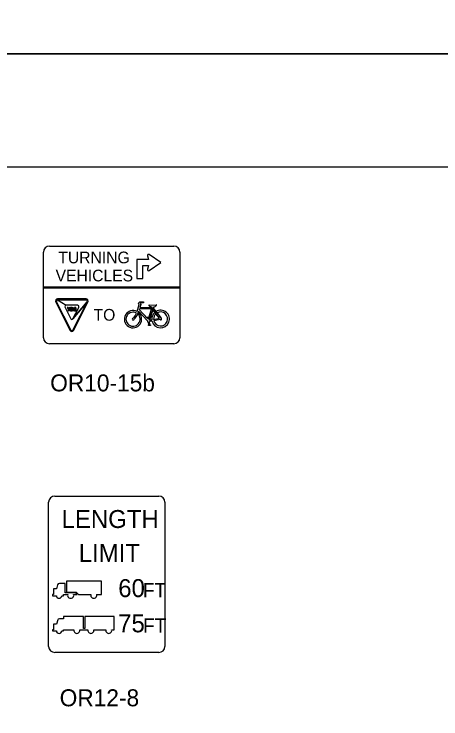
# Model space of a CAD drawing. Extents: x 42133 to 45533, y 41351 to 47951.
# Drawn here: x 42504.5 to 42693.1, y 44357.7 to 44668.9 of the extents above; entities that cross this region are included whole.
import ezdxf

# ---------------------------------------------------------------- set-up
doc = ezdxf.new("R2010")
doc.units = 0
for name, color, linetype in [('#plot_shape', 7, 'Continuous'), ('P_ODOT_PLAN_Border', 7, 'Continuous'), ('P_TRAF_SIGN_SignDetails', 7, 'Continuous')]:
    doc.layers.add(name, color=color, linetype=linetype)

msp = doc.modelspace()

# ---------------------------------------------------------------- linework, layer by layer
at = {"layer": '#plot_shape'}
for points in [[(42133.34, 44651.35), (43833.34, 44651.35), (43833.34, 45751.35), (42133.34, 45751.35)], [(42133.34, 43551.35), (43833.34, 43551.35), (43833.34, 44651.35), (42133.34, 44651.35)]]:
    msp.add_lwpolyline(points, close=True, dxfattribs=at)
at = {"layer": 'P_ODOT_PLAN_Border'}
msp.add_lwpolyline([(42208.34, 43601.35), (43808.34, 43601.35), (43808.34, 44601.35), (42208.34, 44601.35)], close=True, dxfattribs=at)
at = {"layer": 'P_TRAF_SIGN_SignDetails'}
for p, q in [((42517.51, 44526.03), (42517.51, 44563.81)), ((42520.2, 44566.5), (42575.09, 44566.5)), ((42577.79, 44563.81), (42577.79, 44526.03)), ((42517.53, 44547.84), (42517.53, 44548.41)), ((42517.53, 44548.41), (42577.73, 44548.41)), ((42577.73, 44548.41), (42577.73, 44547.84)), ((42577.73, 44547.84), (42517.53, 44547.84)), ((42529.59, 44529.46), (42523.27, 44541.88)), ((42536.39, 44543.18), (42523.74, 44543.18)), ((42536.39, 44543.18), (42523.74, 44543.18)), ((42536.39, 44543.18), (42523.74, 44543.18)), ((42523.74, 44542.81), (42527.51, 44540.34)), ((42523.74, 44542.81), (42536.39, 44542.81)), ((42530.54, 44534.4), (42536.86, 44541.88)), ((42536.86, 44541.88), (42530.54, 44529.46)), ((42536.86, 44541.88), (42530.54, 44534.4)), ((42536.39, 44543.18), (42536.39, 44543.18)), ((42536.39, 44543.18), (42536.39, 44543.18)), ((42522.98, 44541.7), (42529.31, 44529.27)), ((42522.98, 44541.7), (42522.98, 44541.7)), ((42522.98, 44541.7), (42529.31, 44529.27)), ((42522.98, 44541.7), (42522.98, 44541.7)), ((42522.98, 44541.7), (42529.31, 44529.27)), ((42527.04, 44539.41), (42529.59, 44534.39)), ((42532.62, 44540.34), (42527.51, 44540.34)), ((42530.54, 44534.4), (42533.09, 44539.41)), ((42530.82, 44529.27), (42537.15, 44541.7)), ((42530.82, 44529.27), (42537.15, 44541.7)), ((42530.82, 44529.27), (42537.15, 44541.7)), ((42537.15, 44541.7), (42537.15, 44541.7)), ((42537.15, 44541.7), (42537.15, 44541.7)), ((42529.59, 44534.39), (42529.59, 44534.39)), ((42529.31, 44529.27), (42529.31, 44529.27)), ((42529.31, 44529.27), (42529.31, 44529.27)), ((42530.82, 44529.27), (42530.82, 44529.27)), ((42530.82, 44529.27), (42530.82, 44529.27)), ((42575.09, 44523.33), (42520.2, 44523.33)), ((42522.48, 44456.08), (42568.45, 44456.08)), ((42519.79, 44389.7), (42519.79, 44453.39)), ((42571.14, 44453.39), (42571.14, 44389.7)), ((42568.45, 44387), (42522.48, 44387))]:
    msp.add_line(p, q, dxfattribs=at)
for points in [[(42563.45, 44562.15), (42563.94, 44560.55), (42558.68, 44560.55), (42558.68, 44552.13), (42561.35, 44552.13), (42561.35, 44557.88)], [(42563.45, 44562.15), (42563.94, 44560.55), (42558.68, 44560.55), (42558.68, 44552.13), (42561.35, 44552.13), (42561.35, 44557.88)], [(42563.45, 44562.15), (42563.94, 44560.55), (42558.68, 44560.55), (42558.68, 44552.13), (42561.35, 44552.13), (42561.35, 44557.88)], [(42564.24, 44555.71), (42569.36, 44559.22), (42564.24, 44562.73)], [(42564.24, 44555.71), (42569.36, 44559.22), (42564.24, 44562.73)], [(42564.24, 44555.71), (42569.36, 44559.22), (42564.24, 44562.73)], [(42561.35, 44557.88), (42563.94, 44557.88), (42563.45, 44556.29)], [(42561.35, 44557.88), (42563.94, 44557.88), (42563.45, 44556.29)], [(42561.35, 44557.88), (42563.94, 44557.88), (42563.45, 44556.29)], [(42558.84, 44537.56), (42559.85, 44540.67), (42559.38, 44541.16), (42560.14, 44541.9), (42561.75, 44541.9), (42561.75, 44541.35), (42560.38, 44541.35), (42560.19, 44541.13), (42560.58, 44540.73), (42560.11, 44539.36), (42565.42, 44539.38), (42565.51, 44539.68)], [(42558.84, 44537.56), (42559.85, 44540.67), (42559.38, 44541.16), (42560.14, 44541.9), (42561.75, 44541.9), (42561.75, 44541.35), (42560.38, 44541.35), (42560.19, 44541.13), (42560.58, 44540.73)], [(42558.84, 44537.56), (42559.85, 44540.67), (42559.38, 44541.16), (42560.14, 44541.9), (42561.75, 44541.9), (42561.75, 44541.35), (42560.38, 44541.35), (42560.19, 44541.13), (42560.58, 44540.73)], [(42531.6, 44539.35), (42531.26, 44539.35), (42531.26, 44537.87), (42531.44, 44537.87), (42531.6, 44537.87)], [(42531.6, 44538.08), (42531.44, 44538.08), (42531.44, 44539.35), (42531.26, 44539.35), (42531.26, 44537.87), (42531.44, 44537.87), (42531.6, 44537.87)], [(42531.6, 44538.08), (42531.44, 44538.08), (42531.44, 44539.35), (42531.26, 44539.35), (42531.26, 44537.87), (42531.44, 44537.87), (42531.6, 44537.87)], [(42531.6, 44539.35), (42531.44, 44539.35), (42531.44, 44539.15), (42531.6, 44539.15)], [(42531.6, 44539.35), (42531.44, 44539.35), (42531.44, 44539.15), (42531.6, 44539.15)], [(42531.6, 44539.15), (42531.44, 44539.15), (42531.44, 44538.08), (42531.6, 44538.08)], [(42560.58, 44540.73), (42560.11, 44539.36), (42565.42, 44539.38), (42565.22, 44538.71), (42559.88, 44538.67), (42559.8, 44538.43), (42563.42, 44534.45), (42563.42, 44534.8), (42563.16, 44534.8), (42563.16, 44535.15), (42564.01, 44535.15), (42564.01, 44534.8), (42563.87, 44534.8), (42563.87, 44534.2), (42565.51, 44539.68)], [(42560.58, 44540.73), (42560.11, 44539.36), (42565.42, 44539.38), (42565.22, 44538.71), (42559.88, 44538.67), (42559.8, 44538.43), (42563.42, 44534.45), (42563.42, 44534.8), (42563.16, 44534.8), (42563.16, 44535.15), (42564.01, 44535.15), (42564.01, 44534.8), (42563.87, 44534.8), (42563.87, 44534.2), (42565.51, 44539.68)], [(42564.22, 44540.4), (42567.26, 44540.6)], [(42564.22, 44540.4), (42567.26, 44540.6)], [(42564.22, 44540.4), (42567.26, 44540.6)], [(42566.2, 44539.67), (42564.39, 44533.8), (42565.37, 44533.98)], [(42566.2, 44539.67), (42564.39, 44533.8), (42565.37, 44533.98)], [(42566.16, 44534.12), (42568.72, 44534.59), (42565.78, 44538.3), (42566.03, 44539.11), (42569.49, 44534.65)], [(42566.16, 44534.12), (42568.72, 44534.59), (42565.78, 44538.3), (42566.03, 44539.11), (42569.49, 44534.65)], [(42566.2, 44539.67), (42566.03, 44539.11), (42567.2, 44537.6)], [(42563.39, 44533.44), (42559.55, 44537.69), (42559.14, 44536.5)], [(42563.39, 44533.44), (42559.55, 44537.69), (42559.14, 44536.5)], [(42559.15, 44536.5), (42559.39, 44537.21)], [(42559.15, 44536.5), (42559.39, 44537.21)], [(42563.39, 44533.44), (42559.55, 44537.69), (42559.39, 44537.21)], [(42564.39, 44533.8), (42565.78, 44538.3), (42566.66, 44537.19)], [(42566.16, 44534.12), (42568.72, 44534.59), (42567.15, 44536.57)], [(42566.66, 44537.19), (42567.15, 44536.57)], [(42566.66, 44537.19), (42567.15, 44536.57)], [(42567.69, 44536.97), (42567.2, 44537.6)], [(42567.69, 44536.97), (42567.2, 44537.6)], [(42567.69, 44536.97), (42569.49, 44534.65)], [(42564.21, 44532.84), (42564.48, 44531.77), (42564.75, 44531.77), (42564.75, 44531.45), (42563.91, 44531.45), (42563.91, 44531.77), (42564.1, 44531.77), (42563.83, 44532.81)], [(42564.21, 44532.84), (42564.48, 44531.77), (42564.75, 44531.77), (42564.75, 44531.45), (42563.91, 44531.45), (42563.91, 44531.77), (42564.1, 44531.77), (42563.83, 44532.81)], [(42563.91, 44531.77), (42564.1, 44531.77), (42563.83, 44532.81)], [(42564.21, 44532.84), (42564.48, 44531.77), (42564.75, 44531.77), (42564.75, 44531.45), (42563.91, 44531.45), (42563.91, 44531.77)], [(42565.37, 44533.98), (42564.39, 44533.8)], [(42565.48, 44533.33), (42564.5, 44533.14)], [(42565.48, 44533.33), (42564.5, 44533.14)], [(42565.48, 44533.33), (42564.5, 44533.14)], [(42569.07, 44534), (42566.26, 44533.47)], [(42569.07, 44534), (42566.26, 44533.47)], [(42569.07, 44534), (42566.26, 44533.47)], [(42530.82, 44412.55), (42532.45, 44412.55), (42531.77, 44413.29), (42527.11, 44413.29), (42527.11, 44417.44), (42524.58, 44417.44)], [(42530.82, 44412.55), (42532.45, 44412.55), (42531.77, 44413.29), (42527.11, 44413.29), (42527.11, 44417.44), (42524.58, 44417.44)], [(42530.82, 44412.55), (42532.45, 44412.55), (42531.77, 44413.29), (42527.11, 44413.29), (42527.11, 44417.44), (42524.58, 44417.44)], [(42543.09, 44418.47), (42527.64, 44418.47), (42527.64, 44413.68), (42531.98, 44413.68), (42533, 44412.56), (42538.41, 44412.56)], [(42543.09, 44418.47), (42527.64, 44418.47), (42527.64, 44413.68), (42531.98, 44413.68), (42533, 44412.56), (42538.41, 44412.56)], [(42543.09, 44418.47), (42527.64, 44418.47), (42527.64, 44413.68), (42531.98, 44413.68), (42533, 44412.56), (42538.41, 44412.56)], [(42541, 44412.56), (42543.09, 44412.56), (42543.09, 44418.47)], [(42541, 44412.56), (42543.09, 44412.56), (42543.09, 44418.47)], [(42541, 44412.56), (42543.09, 44412.56), (42543.09, 44418.47)], [(42521.94, 44414.92), (42521.94, 44412.55), (42521.46, 44412.55), (42521.46, 44412.07), (42523.19, 44412.07)], [(42521.94, 44414.92), (42521.94, 44412.55), (42521.46, 44412.55), (42521.46, 44412.07), (42523.19, 44412.07)], [(42521.94, 44414.92), (42521.94, 44412.55), (42521.46, 44412.55), (42521.46, 44412.07), (42523.19, 44412.07)], [(42523.76, 44416.81), (42523.32, 44415.09), (42522.11, 44415.09)], [(42523.76, 44416.81), (42523.32, 44415.09), (42522.11, 44415.09)], [(42523.76, 44416.81), (42523.32, 44415.09), (42522.11, 44415.09)], [(42525.62, 44412.07), (42526.32, 44412.07), (42526.32, 44412.55), (42528.2, 44412.55)], [(42525.62, 44412.07), (42526.32, 44412.07), (42526.32, 44412.55), (42528.2, 44412.55)], [(42525.62, 44412.07), (42526.32, 44412.07), (42526.32, 44412.55), (42528.2, 44412.55)], [(42547.63, 44397.02), (42548.73, 44397.02), (42548.73, 44402.94), (42535.82, 44402.94), (42535.82, 44397.55), (42535.18, 44397.55), (42535.18, 44402.94), (42526.31, 44402.94), (42526.31, 44401.91), (42524.51, 44401.91)], [(42547.63, 44397.02), (42548.73, 44397.02), (42548.73, 44402.94), (42535.82, 44402.94), (42535.82, 44397.55), (42535.18, 44397.55), (42535.18, 44402.94), (42526.31, 44402.94), (42526.31, 44401.91), (42524.51, 44401.91)], [(42547.63, 44397.02), (42548.73, 44397.02), (42548.73, 44402.94), (42535.82, 44402.94), (42535.82, 44397.55), (42535.18, 44397.55), (42535.18, 44402.94), (42526.31, 44402.94), (42526.31, 44401.91), (42524.51, 44401.91)], [(42521.94, 44399.38), (42521.94, 44397.02), (42521.46, 44397.02), (42521.46, 44396.54), (42523.19, 44396.54)], [(42521.94, 44399.38), (42521.94, 44397.02), (42521.46, 44397.02), (42521.46, 44396.54), (42523.19, 44396.54)], [(42521.94, 44399.38), (42521.94, 44397.02), (42521.46, 44397.02), (42521.46, 44396.54), (42523.19, 44396.54)], [(42523.78, 44401.35), (42523.32, 44399.55), (42522.11, 44399.55)], [(42523.78, 44401.35), (42523.32, 44399.55), (42522.11, 44399.55)], [(42523.78, 44401.35), (42523.32, 44399.55), (42522.11, 44399.55)], [(42525.61, 44396.54), (42526.31, 44396.54), (42526.31, 44397.02), (42530.93, 44397.02)], [(42525.61, 44396.54), (42526.31, 44396.54), (42526.31, 44397.02), (42530.93, 44397.02)], [(42525.61, 44396.54), (42526.31, 44396.54), (42526.31, 44397.02), (42530.93, 44397.02)], [(42533.55, 44397.02), (42537.16, 44397.02)], [(42533.55, 44397.02), (42537.16, 44397.02)], [(42533.55, 44397.02), (42537.16, 44397.02)], [(42539.78, 44397.02), (42545.01, 44397.02)], [(42539.78, 44397.02), (42545.01, 44397.02)], [(42539.78, 44397.02), (42545.01, 44397.02)]]:
    msp.add_lwpolyline(points, dxfattribs=at)
for points in [[(42528.02, 44539.35), (42528.34, 44538.54), (42528.34, 44537.87), (42528.52, 44537.87), (42528.52, 44538.54), (42528.84, 44539.35), (42528.64, 44539.35), (42528.43, 44538.82), (42528.22, 44539.35)], [(42528.02, 44539.35), (42528.34, 44538.54), (42528.34, 44537.87), (42528.52, 44537.87), (42528.52, 44538.54), (42528.84, 44539.35), (42528.64, 44539.35), (42528.43, 44538.82), (42528.22, 44539.35)], [(42528.02, 44539.35), (42528.34, 44538.54), (42528.34, 44537.87), (42528.52, 44537.87), (42528.52, 44538.54), (42528.84, 44539.35), (42528.64, 44539.35), (42528.43, 44538.82), (42528.22, 44539.35)], [(42529.05, 44539.35), (42529.23, 44539.35), (42529.23, 44537.87), (42529.05, 44537.87)], [(42529.05, 44539.35), (42529.23, 44539.35), (42529.23, 44537.87), (42529.05, 44537.87)], [(42529.05, 44539.35), (42529.23, 44539.35), (42529.23, 44537.87), (42529.05, 44537.87)], [(42529.69, 44538.08), (42529.69, 44538.55), (42529.97, 44538.55), (42529.97, 44538.76), (42529.69, 44538.76), (42529.69, 44539.15), (42530.17, 44539.15), (42530.17, 44539.35), (42529.51, 44539.35), (42529.51, 44537.87), (42530.17, 44537.87), (42530.17, 44538.08)], [(42529.69, 44538.08), (42529.69, 44538.55), (42529.97, 44538.55), (42529.97, 44538.76), (42529.69, 44538.76), (42529.69, 44539.15), (42530.17, 44539.15), (42530.17, 44539.35), (42529.51, 44539.35), (42529.51, 44537.87), (42530.17, 44537.87), (42530.17, 44538.08)], [(42529.69, 44538.08), (42529.69, 44538.55), (42529.97, 44538.55), (42529.97, 44538.76), (42529.69, 44538.76), (42529.69, 44539.15), (42530.17, 44539.15), (42530.17, 44539.35), (42529.51, 44539.35), (42529.51, 44537.87), (42530.17, 44537.87), (42530.17, 44538.08)], [(42530.39, 44539.35), (42530.57, 44539.35), (42530.57, 44538.08), (42531.04, 44538.08), (42531.04, 44537.87), (42530.39, 44537.87)], [(42530.39, 44539.35), (42530.57, 44539.35), (42530.57, 44538.08), (42531.04, 44538.08), (42531.04, 44537.87), (42530.39, 44537.87)], [(42530.39, 44539.35), (42530.57, 44539.35), (42530.57, 44538.08), (42531.04, 44538.08), (42531.04, 44537.87), (42530.39, 44537.87)], [(42559.8, 44538.43), (42563.42, 44534.45), (42563.42, 44534.8), (42563.16, 44534.8), (42563.16, 44535.15), (42564.01, 44535.15), (42564.01, 44534.8), (42563.87, 44534.8), (42563.87, 44534.2), (42565.22, 44538.71), (42559.88, 44538.67)]]:
    msp.add_lwpolyline(points, close=True, dxfattribs=at)
for centre, radius, start, end in [((42520.2, 44563.81), 2.69, 90, 180), ((42575.09, 44563.81), 2.69, 0, 90), ((42563.95, 44562.3), 0.52, 55.6003, 197.0573), ((42563.95, 44562.3), 0.52, 55.6003, 197.0573), ((42563.95, 44562.3), 0.52, 55.6003, 197.0573), ((42563.95, 44556.14), 0.52, 162.9427, 304.3997), ((42563.95, 44556.14), 0.52, 162.9427, 304.3997), ((42563.95, 44556.14), 0.52, 162.9427, 304.3997), ((42564.22, 44540.28), 0.119, 93.7117, 196.8473), ((42564.22, 44540.28), 0.119, 93.7117, 196.8473), ((42564.22, 44540.28), 0.119, 93.7117, 196.8473), ((42564.53, 44540.38), 0.435, 196.8473, 247.1714), ((42564.53, 44540.38), 0.435, 196.8473, 247.1714), ((42564.53, 44540.38), 0.435, 196.8473, 247.1714), ((42565.82, 44543.3), 3.63, 246.2052, 265.1291), ((42565.82, 44543.3), 3.63, 246.2052, 265.1291), ((42565.82, 44543.3), 3.63, 246.2052, 265.1291), ((42566.08, 44541.43), 1.77, 273.7836, 319.0624), ((42566.08, 44541.43), 1.77, 273.7836, 319.0624), ((42566.08, 44541.43), 1.77, 273.7836, 319.0624), ((42567.27, 44540.4), 0.199, 319.0624, 93.7117), ((42567.27, 44540.4), 0.199, 319.0624, 93.7117), ((42567.27, 44540.4), 0.199, 319.0624, 93.7117), ((42557.07, 44534.19), 3.81, 62.2493, 52.53), ((42557.07, 44534.19), 3.81, 62.2493, 52.4985), ((42557.07, 44534.19), 3.81, 62.2493, 52.4985), ((42557.07, 44534.19), 3.11, 59.9908, 48.0532), ((42557.07, 44534.19), 3.11, 59.9908, 48.0133), ((42557.07, 44534.19), 3.11, 59.9908, 48.0133), ((42554.16, 44538.35), 4.7, 308.2875, 341.8191), ((42554.16, 44538.35), 4.7, 308.2875, 341.8191), ((42554.16, 44538.35), 4.7, 308.2875, 341.8191), ((42554.61, 44538.03), 4.79, 307.7974, 341.3197), ((42554.61, 44538.03), 4.79, 307.7974, 341.3197), ((42554.61, 44538.03), 4.79, 307.7974, 341.3197), ((42569.26, 44534.29), 3.9, 131.8798, 184.5252), ((42569.26, 44534.29), 3.9, 131.909, 184.5252), ((42569.26, 44534.29), 3.9, 131.909, 184.5252), ((42569.26, 44534.29), 3.9, 194.2461, 121.8851), ((42569.26, 44534.29), 3.9, 194.2461, 121.8558), ((42569.26, 44534.29), 3.9, 194.2461, 121.8558), ((42569.26, 44534.29), 3.11, 132.7787, 183.036), ((42569.26, 44534.29), 3.11, 132.8154, 183.036), ((42569.26, 44534.29), 3.11, 132.8154, 183.036), ((42569.26, 44534.29), 3.11, 195.1748, 120.3535), ((42569.26, 44534.29), 3.11, 195.1748, 120.3165), ((42569.26, 44534.29), 3.11, 195.1748, 120.3165), ((42557.14, 44534.26), 0.405, 99.9437, 358.8663), ((42557.14, 44534.26), 0.405, 99.9437, 358.8663), ((42557.14, 44534.26), 0.405, 99.9437, 358.8663), ((42563.97, 44533.37), 0.581, 173.0491, 255.861), ((42563.97, 44533.37), 0.581, 173.0491, 255.861), ((42563.97, 44533.37), 0.581, 173.0491, 255.861), ((42563.97, 44533.37), 0.581, 294.6322, 336.7292), ((42563.97, 44533.37), 0.581, 294.6322, 336.7292), ((42563.97, 44533.37), 0.581, 294.6322, 336.7292), ((42569.3, 44534.31), 0.391, 233.7627, 60.8531), ((42569.3, 44534.31), 0.391, 233.7627, 60.8531), ((42569.3, 44534.31), 0.391, 233.7627, 60.8531), ((42520.2, 44526.03), 2.69, 180, 270), ((42575.09, 44526.03), 2.69, 270, 0), ((42522.48, 44453.39), 2.69, 90, 180), ((42568.45, 44453.39), 2.69, 0, 90), ((42524.58, 44416.6), 0.846, 90, 165.6407), ((42524.58, 44416.6), 0.846, 90, 165.6407), ((42524.58, 44416.6), 0.846, 90, 165.6407), ((42522.11, 44414.92), 0.169, 90, 180), ((42522.11, 44414.92), 0.169, 90, 180), ((42522.11, 44414.92), 0.169, 90, 180), ((42524.41, 44412.18), 1.22, 185.085, 354.915), ((42524.41, 44412.18), 1.22, 185.085, 354.915), ((42524.41, 44412.18), 1.22, 185.085, 354.915), ((42529.51, 44412.3), 1.34, 168.9606, 11.0394), ((42529.51, 44412.3), 1.34, 168.9606, 11.0394), ((42529.51, 44412.3), 1.34, 168.9606, 11.0394), ((42539.71, 44412.28), 1.33, 167.9862, 12.0138), ((42539.71, 44412.28), 1.33, 167.9862, 12.0138), ((42539.71, 44412.28), 1.33, 167.9862, 12.0138), ((42524.51, 44401.16), 0.752, 90, 165.5587), ((42524.51, 44401.16), 0.752, 90, 165.5587), ((42524.51, 44401.16), 0.752, 90, 165.5587), ((42522.11, 44399.38), 0.169, 90, 180), ((42522.11, 44399.38), 0.169, 90, 180), ((42522.11, 44399.38), 0.169, 90, 180), ((42524.4, 44396.63), 1.22, 184.479, 355.521), ((42524.4, 44396.63), 1.22, 184.479, 355.521), ((42524.4, 44396.63), 1.22, 184.479, 355.521), ((42532.24, 44396.75), 1.33, 168.2436, 11.7564), ((42532.24, 44396.75), 1.33, 168.2436, 11.7564), ((42532.24, 44396.75), 1.33, 168.2436, 11.7564), ((42538.47, 44396.75), 1.33, 168.2436, 11.7564), ((42538.47, 44396.75), 1.33, 168.2436, 11.7564), ((42538.47, 44396.75), 1.33, 168.2436, 11.7564), ((42546.32, 44396.75), 1.33, 168.2437, 11.7563), ((42546.32, 44396.75), 1.33, 168.2437, 11.7563), ((42546.32, 44396.75), 1.33, 168.2437, 11.7563), ((42522.48, 44389.7), 2.69, 180, 270), ((42568.45, 44389.7), 2.69, 270, 0)]:
    msp.add_arc(centre, radius, start, end, dxfattribs=at)
for centre, major_axis, ratio, start_param, end_param in [((42523.74, 44542.19), (0, 0.987), 0.882166, 6.274175, 8.377587), ((42523.74, 44542.19), (0, 0.987), 0.881814, 0, 2.094395), ((42523.74, 44542.19), (0, 0.987), 0.881814, 0, 2.094395), ((42523.74, 44542.19), (0, 0.617), 0.882166, 6.271789, 8.377588), ((42536.39, 44542.19), (0, 0.987), 0.882166, 4.188759, 6.283213), ((42536.39, 44542.19), (0, 0.987), 0.881814, 4.188963, 6.283358), ((42536.39, 44542.19), (0, 0.987), 0.881814, 4.188963, 6.283358), ((42536.39, 44542.19), (0, 0.617), 0.882166, 4.188768, 6.283222), ((42527.51, 44539.72), (0, -0.617), 0.882166, 3.141593, 5.235988), ((42531.6, 44539), (0, 0.353), 0.868587, 5.256629, 6.310275), ((42531.6, 44539), (0, 0.353), 0.868587, 5.256629, 6.310275), ((42531.6, 44539), (0, 0.353), 0.868587, 5.256629, 6.310275), ((42531.6, 44538.99), (0, 0.16), 0.868587, 5.295684, 6.282002), ((42531.6, 44538.99), (0, 0.16), 0.868587, 5.295684, 6.282002), ((42531.6, 44538.99), (0, 0.16), 0.868587, 5.295684, 6.282002), ((42531.5, 44538.87), (0, 0.321), 0.868587, 4.8494, 5.407163), ((42531.5, 44538.87), (0, 0.321), 0.868587, 4.8494, 5.407163), ((42531.5, 44538.87), (0, 0.321), 0.868587, 4.8494, 5.407163), ((42529.82, 44538.58), (0, 2.27), 0.868587, 4.728766, 4.861182), ((42529.82, 44538.58), (0, 2.27), 0.868587, 4.728766, 4.861182), ((42529.82, 44538.58), (0, 2.27), 0.868587, 4.728766, 4.861182), ((42531.45, 44538.85), (0, 0.581), 0.868587, 4.809996, 5.326895), ((42531.45, 44538.85), (0, 0.581), 0.868587, 4.809996, 5.326895), ((42531.45, 44538.85), (0, 0.581), 0.868587, 4.809996, 5.326895), ((42530.35, 44538.61), (0, 1.88), 0.868587, 4.713879, 4.870255), ((42530.35, 44538.61), (0, 1.88), 0.868587, 4.713879, 4.870255), ((42530.35, 44538.61), (0, 1.88), 0.868587, 4.713879, 4.870255), ((42532.62, 44539.72), (0, 0.617), 0.882166, 4.18879, 6.283185), ((42531.6, 44538.24), (0, 0.16), 0.868587, 3.142776, 4.129094), ((42531.6, 44538.24), (0, 0.16), 0.868587, 3.142776, 4.129094), ((42531.6, 44538.24), (0, 0.16), 0.868587, 3.142776, 4.129094), ((42531.6, 44538.22), (0, 0.353), 0.868587, 3.114503, 4.168149), ((42531.6, 44538.22), (0, 0.353), 0.868587, 3.114503, 4.168149), ((42531.6, 44538.22), (0, 0.353), 0.868587, 3.114503, 4.168149), ((42531.5, 44538.36), (0, 0.321), 0.868587, 4.017615, 4.575378), ((42531.5, 44538.36), (0, 0.321), 0.868587, 4.017615, 4.575378), ((42531.5, 44538.36), (0, 0.321), 0.868587, 4.017615, 4.575378), ((42529.82, 44538.65), (0, 2.27), 0.868587, 4.563596, 4.696012), ((42529.82, 44538.65), (0, 2.27), 0.868587, 4.563596, 4.696012), ((42529.82, 44538.65), (0, 2.27), 0.868587, 4.563596, 4.696012), ((42531.45, 44538.38), (0, 0.581), 0.868587, 4.097883, 4.614782), ((42531.45, 44538.38), (0, 0.581), 0.868587, 4.097883, 4.614782), ((42531.45, 44538.38), (0, 0.581), 0.868587, 4.097883, 4.614782), ((42530.35, 44538.62), (0, 1.88), 0.868587, 4.554523, 4.710899), ((42530.35, 44538.62), (0, 1.88), 0.868587, 4.554523, 4.710899), ((42530.35, 44538.62), (0, 1.88), 0.868587, 4.554523, 4.710899), ((42530.06, 44534.7), (0, -0.617), 0.882166, 5.235988, 7.337018), ((42530.06, 44529.77), (0, 0.617), 0.882166, 2.094395, 4.188789), ((42530.06, 44529.77), (0, 0.987), 0.882166, 2.094395, 4.188789), ((42530.06, 44529.77), (0, 0.987), 0.881814, 2.094222, 4.188617), ((42530.06, 44529.77), (0, 0.987), 0.881814, 2.094222, 4.188617)]:
    msp.add_ellipse(centre, major_axis=major_axis, ratio=ratio, start_param=start_param, end_param=end_param, dxfattribs=at)

# ---------------------------------------------------------------- texts
for s, height, p in [('TURNING', 5.176, (42524.06, 44558.86)), ('VEHICLES', 5.176, (42522.86, 44550.89)), ('TO', 5.176, (42539.63, 44533.53)), ('OR10-15b', 7.5, (42520.47, 44502.31)), ('LENGTH', 7.918, (42525.49, 44441.99)), ('LIMIT', 7.918, (42533.07, 44427.02)), ('60', 7.918, (42550.53, 44411.47)), ('FT', 6.335, (42561.39, 44411.32)), ('75', 7.918, (42550.5, 44395.91)), ('FT', 6.335, (42561.46, 44395.69)), ('OR12-8', 7.5, (42524.65, 44363.24))]:
    msp.add_text(s, height=height, dxfattribs=at).set_placement(p)

doc.saveas('drawing.dxf')
